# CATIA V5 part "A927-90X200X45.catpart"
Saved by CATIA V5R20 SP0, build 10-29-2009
Part number: A927-90X200X45
Source: Unknown
Property "A": "50.000"
Property "ARTICLENO": "A927-90X200X45"
Property "BOMINFO": "A927-90X200X45"
Property "CODE": "A927-90X200X45"
Property "CREATOR": "CADENAS GmbH"
Property "D": "18.000"
Property "D1": "26.000"
Property "F": "28.000"
Property "FORM": "A"
Property "L": "200.000"
Property "L1": "100.000"
Property "L2": "20.000"
Property "L3": "50.000"
Property "LINA": "A927-90X200X45"
Property "NB": "A927-90X200X45"
Property "NBSYN": "$CODE."
Property "NN": "A927"
Property "NT": "VDI 3387 Removable Die Heels, steel and self-lubricating"
Property "R": "25.000"
Property "S": "45.000"
Property "SUPPLIER": "CF"
Property "T": "21.000"
Property "W": "90.000"
Bounding box of the stored display mesh (mm): x -45 to 45, y 0 to 200, z -45 to 0
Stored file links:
  C:\Users\borellobunino\Desktop\3D X SITO CF\A927\GSB_OILLESS_G2290509020045\CATIAV5\A927-90X200X45.catpart
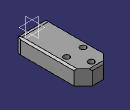
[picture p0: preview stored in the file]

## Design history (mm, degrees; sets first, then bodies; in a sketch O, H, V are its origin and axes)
Body1 "Geometry.1" (main body)
  Solid1 "A927-90X200X45.catpart": solid without history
